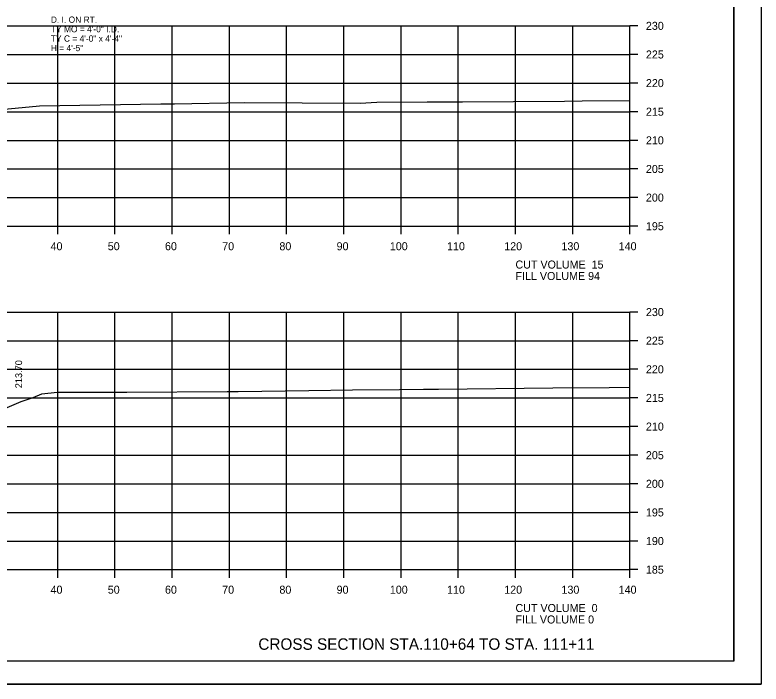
# Model space of a CAD drawing. Extents: x 1368968 to 1369915, y 377395 to 380381.
# Drawn here: x 1369784.3 to 1369914.7, y 377394.7 to 377511.6 of the extents above; entities that cross this region are included whole.
import ezdxf

# ---------------------------------------------------------------- set-up
doc = ezdxf.new("R2010")
doc.units = 0
for name, color, linetype in [('Default', 7, 'Continuous'), ('S_BREAKLINE_ANNOT', 7, 'Continuous'), ('S_BRIDGE', 7, 'Continuous'), ('S_BRIDGE_ANNOT', 7, 'Continuous'), ('S_CONTOUR_MINOR', 7, 'Continuous'), ('S_CTL_TABLE', 7, 'Continuous'), ('S_DITCHLINE_ANNOT', 7, 'Continuous'), ('S_DROP_INLET', 7, 'Continuous'), ('S_EXISTING_ALIGNMENT_ANNOT', 7, 'Continuous')]:
    doc.layers.add(name, color=color, linetype=linetype)

msp = doc.modelspace()

# ---------------------------------------------------------------- linework, layer by layer
at = {"layer": 'S_BREAKLINE_ANNOT'}
for p, q in [((1369891.78, 377474.68), (1369891.78, 377509.68)), ((1369893.18, 377509.68), (1369891.78, 377509.68)), ((1369893.18, 377504.68), (1369891.78, 377504.68)), ((1369893.18, 377499.68), (1369891.78, 377499.68)), ((1369893.18, 377494.68), (1369891.78, 377494.68)), ((1369893.18, 377489.68), (1369891.78, 377489.68)), ((1369893.18, 377484.68), (1369891.78, 377484.68)), ((1369893.18, 377479.68), (1369891.78, 377479.68)), ((1369611.78, 377474.68), (1369891.78, 377474.68)), ((1369791.78, 377473.28), (1369791.78, 377474.68)), ((1369801.78, 377473.28), (1369801.78, 377474.68)), ((1369811.78, 377473.28), (1369811.78, 377474.68)), ((1369821.78, 377473.28), (1369821.78, 377474.68)), ((1369831.78, 377473.28), (1369831.78, 377474.68)), ((1369841.78, 377473.28), (1369841.78, 377474.68)), ((1369851.78, 377473.28), (1369851.78, 377474.68)), ((1369861.78, 377473.28), (1369861.78, 377474.68)), ((1369871.78, 377473.28), (1369871.78, 377474.68)), ((1369881.78, 377473.28), (1369881.78, 377474.68)), ((1369891.78, 377473.28), (1369891.78, 377474.68)), ((1369893.18, 377474.68), (1369891.78, 377474.68)), ((1369891.78, 377414.68), (1369891.78, 377459.68)), ((1369893.18, 377459.68), (1369891.78, 377459.68)), ((1369893.18, 377454.68), (1369891.78, 377454.68)), ((1369893.18, 377449.68), (1369891.78, 377449.68)), ((1369893.18, 377444.68), (1369891.78, 377444.68)), ((1369893.18, 377439.68), (1369891.78, 377439.68)), ((1369893.18, 377434.68), (1369891.78, 377434.68)), ((1369893.18, 377429.68), (1369891.78, 377429.68)), ((1369893.18, 377424.68), (1369891.78, 377424.68)), ((1369893.18, 377419.68), (1369891.78, 377419.68)), ((1369611.78, 377414.68), (1369891.78, 377414.68)), ((1369791.78, 377413.28), (1369791.78, 377414.68)), ((1369801.78, 377413.28), (1369801.78, 377414.68)), ((1369811.78, 377413.28), (1369811.78, 377414.68)), ((1369821.78, 377413.28), (1369821.78, 377414.68)), ((1369831.78, 377413.28), (1369831.78, 377414.68)), ((1369841.78, 377413.28), (1369841.78, 377414.68)), ((1369851.78, 377413.28), (1369851.78, 377414.68)), ((1369861.78, 377413.28), (1369861.78, 377414.68)), ((1369871.78, 377413.28), (1369871.78, 377414.68)), ((1369881.78, 377413.28), (1369881.78, 377414.68)), ((1369891.78, 377413.28), (1369891.78, 377414.68)), ((1369893.18, 377414.68), (1369891.78, 377414.68))]:
    msp.add_line(p, q, dxfattribs=at)
at = {"layer": 'S_BRIDGE_ANNOT'}
for q in [(1369909.96, 377604.14), (1369593.78, 377398.68)]:
    msp.add_line((1369909.96, 377398.68), q, dxfattribs=at)
at = {"layer": 'S_CTL_TABLE'}
for points in [[(1369779.37, 377494.85), (1369788.61, 377495.68), (1369809.82, 377496.03), (1369812.19, 377496.07), (1369824.35, 377496.29), (1369844.64, 377496.19), (1369847.57, 377496.35), (1369856.32, 377496.42), (1369862.51, 377496.43), (1369880.34, 377496.55), (1369883.42, 377496.57), (1369891.78, 377496.63)], [(1369782.91, 377443.02), (1369785.4, 377444.06), (1369787.49, 377444.75), (1369789.02, 377445.38), (1369791.67, 377445.67), (1369796.88, 377445.67), (1369803.86, 377445.71), (1369821.37, 377445.8), (1369822, 377445.8), (1369822.33, 377445.81), (1369822.57, 377445.81), (1369823.32, 377445.82), (1369835.69, 377446), (1369843.32, 377446.08), (1369851.53, 377446.15), (1369855.68, 377446.21), (1369856.49, 377446.21), (1369858.35, 377446.23), (1369878.33, 377446.45), (1369888.14, 377446.5), (1369891.78, 377446.54)]]:
    msp.add_lwpolyline(points, dxfattribs=at)
at = {"layer": 'S_DITCHLINE_ANNOT'}
for p, q in [((1369611.78, 377509.68), (1369891.78, 377509.68)), ((1369791.78, 377474.68), (1369791.78, 377509.68)), ((1369801.78, 377474.68), (1369801.78, 377509.68)), ((1369811.78, 377474.68), (1369811.78, 377509.68)), ((1369821.78, 377474.68), (1369821.78, 377509.68)), ((1369831.78, 377474.68), (1369831.78, 377509.68)), ((1369841.78, 377474.68), (1369841.78, 377509.68)), ((1369851.78, 377474.68), (1369851.78, 377509.68)), ((1369861.78, 377474.68), (1369861.78, 377509.68)), ((1369871.78, 377474.68), (1369871.78, 377509.68)), ((1369881.78, 377474.68), (1369881.78, 377509.68)), ((1369891.78, 377474.68), (1369891.78, 377509.68)), ((1369611.78, 377504.68), (1369891.78, 377504.68)), ((1369611.78, 377499.68), (1369891.78, 377499.68)), ((1369611.78, 377494.68), (1369891.78, 377494.68)), ((1369611.78, 377489.68), (1369891.78, 377489.68)), ((1369611.78, 377484.68), (1369891.78, 377484.68)), ((1369611.78, 377479.68), (1369891.78, 377479.68)), ((1369611.78, 377474.68), (1369891.78, 377474.68)), ((1369611.78, 377459.68), (1369891.78, 377459.68)), ((1369791.78, 377414.68), (1369791.78, 377459.68)), ((1369801.78, 377414.68), (1369801.78, 377459.68)), ((1369811.78, 377414.68), (1369811.78, 377459.68)), ((1369821.78, 377414.68), (1369821.78, 377459.68)), ((1369831.78, 377414.68), (1369831.78, 377459.68)), ((1369841.78, 377414.68), (1369841.78, 377459.68)), ((1369851.78, 377414.68), (1369851.78, 377459.68)), ((1369861.78, 377414.68), (1369861.78, 377459.68)), ((1369871.78, 377414.68), (1369871.78, 377459.68)), ((1369881.78, 377414.68), (1369881.78, 377459.68)), ((1369891.78, 377414.68), (1369891.78, 377459.68)), ((1369611.78, 377454.68), (1369891.78, 377454.68)), ((1369611.78, 377449.68), (1369891.78, 377449.68)), ((1369611.78, 377444.68), (1369891.78, 377444.68)), ((1369611.78, 377439.68), (1369891.78, 377439.68)), ((1369611.78, 377434.68), (1369891.78, 377434.68)), ((1369611.78, 377429.68), (1369891.78, 377429.68)), ((1369611.78, 377424.68), (1369891.78, 377424.68)), ((1369611.78, 377419.68), (1369891.78, 377419.68)), ((1369611.78, 377414.68), (1369891.78, 377414.68))]:
    msp.add_line(p, q, dxfattribs=at)
at = {"layer": 'S_DROP_INLET'}
msp.add_line((1369581.38, 377394.7), (1369914.71, 377394.7), dxfattribs=at)
for points in [[(1369581.37, 377608.03), (1369914.71, 377608.03), (1369914.71, 377394.69), (1369581.37, 377394.69)], [(1369827.7, 377604.14), (1369827.7, 377594.26), (1369863.43, 377594.26), (1369863.43, 377591.34), (1369886.63, 377591.34), (1369886.63, 377567), (1369909.96, 377567), (1369909.96, 377398.68), (1369593.78, 377398.68), (1369593.78, 377604.14)]]:
    msp.add_lwpolyline(points, close=True, dxfattribs=at)

# ---------------------------------------------------------------- texts
at = {"layer": 'Default'}
for s, p in [('D. I. ON RT.', (1369790.57, 377510.21)), ('TY MO = 4\'-0" I.D.', (1369790.57, 377508.56)), ('TY C = 4\'-0" x 4\'-4"', (1369790.57, 377506.91)), ('H = 4\'-5"', (1369790.57, 377505.26))]:
    msp.add_text(s, height=1.1, dxfattribs=at).set_placement(p)
at = {"layer": 'S_BRIDGE'}
for s, p in [('230', (1369894.58, 377508.98)), ('225', (1369894.58, 377503.98)), ('220', (1369894.58, 377498.98)), ('215', (1369894.58, 377493.98)), ('210', (1369894.58, 377488.98)), ('205', (1369894.58, 377483.98)), ('200', (1369894.58, 377478.98)), ('195', (1369894.58, 377473.98)), ('40', (1369790.52, 377470.48)), ('50', (1369800.52, 377470.48)), ('60', (1369810.52, 377470.48)), ('70', (1369820.52, 377470.48)), ('80', (1369830.52, 377470.48)), ('90', (1369840.52, 377470.48)), ('100', (1369849.82, 377470.48)), ('110', (1369859.82, 377470.48)), ('120', (1369869.82, 377470.48)), ('130', (1369879.82, 377470.48)), ('140', (1369889.82, 377470.48)), ('CUT VOLUME  15', (1369871.78, 377467.28)), ('FILL VOLUME 94', (1369871.78, 377465.28)), ('230', (1369894.58, 377458.98)), ('225', (1369894.58, 377453.98)), ('220', (1369894.58, 377448.98)), ('215', (1369894.58, 377443.98)), ('210', (1369894.58, 377438.98)), ('205', (1369894.58, 377433.98)), ('200', (1369894.58, 377428.98)), ('195', (1369894.58, 377423.98)), ('190', (1369894.58, 377418.98)), ('185', (1369894.58, 377413.98)), ('40', (1369790.52, 377410.48)), ('50', (1369800.52, 377410.48)), ('60', (1369810.52, 377410.48)), ('70', (1369820.52, 377410.48)), ('80', (1369830.52, 377410.48)), ('90', (1369840.52, 377410.48)), ('100', (1369849.82, 377410.48)), ('110', (1369859.82, 377410.48)), ('120', (1369869.82, 377410.48)), ('130', (1369879.82, 377410.48)), ('140', (1369889.82, 377410.48)), ('CUT VOLUME  0', (1369871.78, 377407.28)), ('FILL VOLUME 0', (1369871.78, 377405.28))]:
    msp.add_text(s, height=1.4, dxfattribs=at).set_placement(p)
at = {"layer": 'S_CONTOUR_MINOR'}
msp.add_text('CROSS SECTION STA.110+64 TO STA. 111+11', height=2, dxfattribs=at).set_placement((1369826.84, 377400.68))
at = {"layer": 'S_EXISTING_ALIGNMENT_ANNOT'}
msp.add_text('213.70', height=1.2, rotation=90, dxfattribs=at).set_placement((1369785.55, 377446.37))

doc.saveas('drawing.dxf')
